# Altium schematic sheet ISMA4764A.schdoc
size 127 x 101 mm
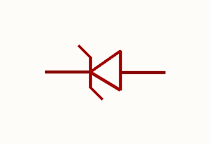
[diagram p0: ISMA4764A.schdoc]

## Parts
D?  1sma4764a_c173482  [SMA_L4.4-W2.6-LS5.0-RD]  (value not drawn)

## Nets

Not connected (* = marked no-connect by the designer): D? 1(C) 2(A)

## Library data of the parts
D? = 1sma4764a_c173482: 二极管配置:1个独立式;稳压值(标称值):100V;稳压值(范围):95V~105V;耗散功率(Pd):1W;; Manufacturer: MDD(辰达半导体); Symbol: ISMA4764A; AddInBom: yes; ModelId: a2d22152f8d5421c8e96dbd56af7c345; ModelTransform: 204.724,98.425,0,0,0,0,0,0,0; Diode Configuration: 1个独立式; Zener Voltage(Nom): 100V; Reverse Leakage Current (Ir): 1uA; Pd - Power Dissipation: 1W; Impedance(Zzt): 350Ω; Operating Junction Temperature Range: -55℃~+150℃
